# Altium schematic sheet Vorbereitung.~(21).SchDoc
size A4
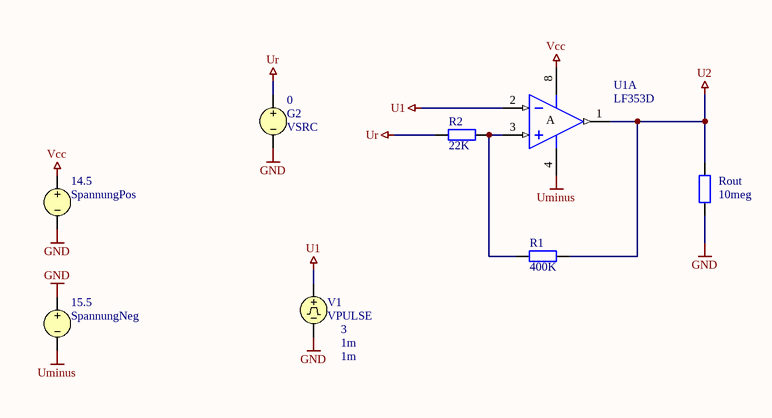
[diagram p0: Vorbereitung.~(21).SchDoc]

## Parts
G2  VSRC  value 0
R1  value 400K  [AXIAL-0.4]  (hidden comment: Res2)
R2  value 22K  [AXIAL-0.4]  (hidden comment: Res2)
Rout  value 10meg  [AXIAL-0.4]  (hidden comment: Res2)
SpannungNeg  value 15.5  (hidden comment: VSRC)
SpannungPos  value 14.5  (hidden comment: VSRC)
U1  LF353D  [D008_L]  (part A of 2)
V1  VPULSE  AC Magnitude: 3  Rise Time: 1m

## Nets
GND: G2.2 Rout.1 SpannungNeg.1 SpannungPos.2 V1.2
U1: U1.2(IN-) V1.1
U2: R1.1 Rout.2 U1.1(OUT)
Uminus: SpannungNeg.2 U1.4(V-)
Ur: G2.1 R2.2
Vcc: SpannungPos.1 U1.8(V+)
NetR1_2: R1.2 R2.1 U1.3(IN+)

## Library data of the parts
G2 SpannungNeg SpannungPos = VSRC: Voltage Source; Note: PCB Footprint - Not required
R1 R2 Rout = Res2: Resistor
U1 = LF353D: Dual Operational Amplifier
V1 = VPULSE: Pulse Voltage Source; Note: PCB Footprint - Not required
